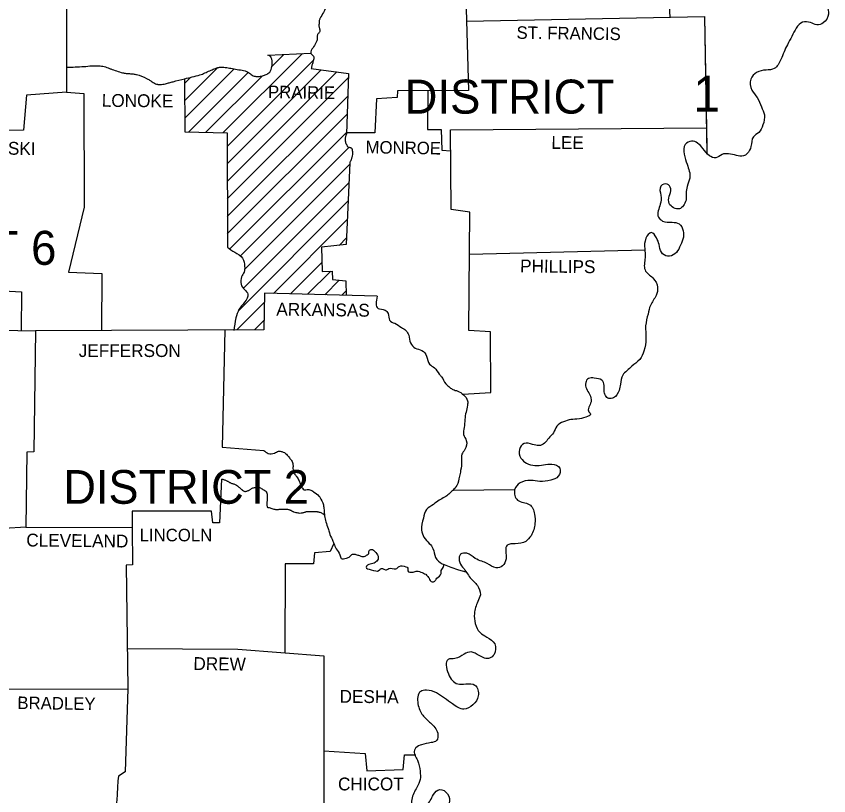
# Model space of a CAD drawing. Extents: x 982240 to 1103002, y 974866 to 1054902.
# Drawn here: x 1087558 to 1097361, y 1031353 to 1040761 of the extents above; entities that cross this region are included whole.
import ezdxf

# ---------------------------------------------------------------- set-up
doc = ezdxf.new("R2010")
doc.units = 0
for name, color, linetype in [('1', 7, 'Continuous'), ('Default', 7, 'Continuous'), ('R_Draft', 7, 'Continuous')]:
    doc.layers.add(name, color=color, linetype=linetype)

msp = doc.modelspace()

# ---------------------------------------------------------------- linework, layer by layer
at = {"layer": '1'}
for points in [[(1087926.5, 1048089), (1087933.9, 1047210.6), (1087872.7, 1047207), (1087883.5, 1046310.6), (1087631.5, 1046274.6), (1087653.1, 1046033.4), (1087739.5, 1045921.8), (1087732.3, 1045637.4), (1087242.7, 1045619.4), (1087224.7, 1045180.2), (1086778.3, 1045165.8), (1086756.7, 1044633), (1086781.9, 1044589.8), (1086792.7, 1043740.2), (1087563.1, 1043689.8), (1087552.3, 1041792.6), (1088164.3, 1041774.6), (1088164.3, 1039845), (1087681.9, 1039809), (1087645.9, 1039384.2), (1086835.9, 1039380.6)], [(1090594.2, 1040291.4), (1091112.1, 1040316.4)], [(1091116.2, 1040129.4), (1091566.2, 1040071.8), (1091541, 1039337.4)], [(1091580.6, 1038991.8), (1091537.4, 1038005.4), (1091242.2, 1037973), (1091249.4, 1037681.4), (1091368.2, 1037685), (1091371.8, 1037584.2), (1091533.8, 1037566.2), (1091539.1, 1037392.5)], [(1091911.8, 1037382.6), (1090551, 1037418.6), (1090543.8, 1036975.8), (1087789.9, 1036965)], [(1085716.3, 1036489.8), (1085917.9, 1036518.6), (1085932.3, 1036641), (1086051.1, 1036662.6), (1086058.3, 1036734.6), (1086897.1, 1036759.8), (1086929.5, 1036979.4), (1087789.9, 1036965)], [(1087674.7, 1034596.2), (1087148.3, 1034563.8)], [(1087674.7, 1034596.2), (1088957.3, 1034589)], [(1088957.3, 1034589), (1088959.9, 1034139), (1088884.3, 1034135.4), (1088905.9, 1032641.4)], [(1092721.8, 1034142.6), (1092802.4, 1034111), (1092894.8, 1034078.9), (1092982.6, 1034056.4)], [(1088905.9, 1032641.4), (1088869.9, 1031640.6), (1088790.7, 1031590.2)]]:
    msp.add_lwpolyline(points, dxfattribs=at)
for points in [[(1091573.4, 1042253.4), (1091571.2, 1042223.5), (1091568.5, 1042193.6), (1091563.7, 1042164), (1091560.1, 1042149.3), (1091557.9, 1042141.9), (1091555.4, 1042134.6), (1091543.7, 1042121.4), (1091525.3, 1042115.1), (1091504.8, 1042110.4), (1091495.2, 1042107.1), (1091487, 1042102.2), (1091444.9, 1042065.1), (1091407.8, 1042023), (1091401, 1042006), (1091399.3, 1041986.5), (1091397.4, 1041967.2), (1091389.8, 1041951), (1091383.2, 1041945.5), (1091375.5, 1041941.5), (1091357.9, 1041936.3), (1091340, 1041931.2), (1091325, 1041922.2), (1091308, 1041905), (1091291.9, 1041887), (1091277, 1041867.7), (1091263.8, 1041846.6), (1091239, 1041795.5), (1091224.2, 1041742.2), (1091221.3, 1041688.3), (1091224.2, 1041634.2), (1091226.7, 1041603.1), (1091231, 1041572.3), (1091238.1, 1041541.9), (1091243.2, 1041526.8), (1091249.4, 1041511.8), (1091266.2, 1041497.3), (1091291.2, 1041493.3), (1091317.8, 1041490.5), (1091339.4, 1041479.4), (1091346.6, 1041471.2), (1091353.2, 1041462.8), (1091365, 1041445.1), (1091382.6, 1041407.4), (1091383.5, 1041388.8), (1091378.2, 1041369.1), (1091373.3, 1041349.7), (1091375.4, 1041331.8), (1091392.2, 1041316), (1091417.1, 1041307.4), (1091442.8, 1041298.4), (1091461.8, 1041281.4), (1091468, 1041270.7), (1091473.6, 1041259.9), (1091476.9, 1041249.1), (1091476.2, 1041238.2), (1091461.8, 1041191.4), (1091422.2, 1041058.2), (1091419.4, 1041036.1), (1091421.2, 1041013.6), (1091424.4, 1040990.9), (1091425.8, 1040968.2), (1091424.3, 1040948.3), (1091422.1, 1040938.4), (1091418.6, 1040928.6), (1091399.7, 1040915.1), (1091371, 1040914.6), (1091341.8, 1040914.9), (1091321.4, 1040903.4), (1091263.8, 1040806.2), (1091224.2, 1040737.8), (1091219.3, 1040726.7), (1091211.9, 1040693), (1091210.6, 1040670.4), (1091209.8, 1040647.8), (1091211.5, 1040631.6), (1091216, 1040615.4), (1091220.2, 1040599.2), (1091220.6, 1040583), (1091215.6, 1040569.6), (1091207, 1040557.4), (1091198, 1040545.4), (1091191.8, 1040532.6), (1091189, 1040514), (1091188.4, 1040494.4), (1091186.8, 1040475), (1091181, 1040457), (1091145, 1040392.2), (1091112.6, 1040331), (1091113.9, 1040313.3), (1091127.9, 1040295.5), (1091143.3, 1040277.5), (1091148.6, 1040259), (1091143.6, 1040234.1), (1091137.8, 1040208.6), (1091132.2, 1040188.7), (1091125.9, 1040168.9), (1091116.2, 1040129.4)], [(1097203.6, 1042109.4), (1097218, 1042005), (1097156.9, 1041893.4), (1097135.3, 1041781.8), (1097146.1, 1041670.2), (1097030.9, 1041609), (1096930.1, 1041537), (1096987.7, 1041450.6), (1097095.7, 1041371.4), (1097203.6, 1041310.2), (1097272, 1041249), (1097290, 1041101.4), (1097308, 1041007.8), (1097344, 1040878.2), (1097358.4, 1040788.2), (1097293.6, 1040680.2), (1097218, 1040658.6), (1097138.9, 1040683.8), (1097045.3, 1040691), (1096969.7, 1040619), (1096915.7, 1040518.2), (1096861.7, 1040417.4), (1096822.1, 1040331), (1096782.5, 1040237.4), (1096703.3, 1040129.4), (1096606.1, 1040111.4), (1096490.9, 1040082.6), (1096422.5, 1040003.4), (1096433.3, 1039870.2), (1096498.1, 1039780.2), (1096548.5, 1039668.6), (1096584.5, 1039571.4), (1096566.5, 1039449), (1096516.1, 1039359), (1096451.3, 1039305), (1096422.5, 1039189.8), (1096375.7, 1039103.4), (1096332.5, 1039074.6), (1096246.1, 1039081.8), (1096152.5, 1039099.8), (1096073.3, 1039092.6), (1095997.7, 1039053), (1095922.1, 1039078.2), (1095842.9, 1039164.6), (1095778.1, 1039229.4), (1095706.1, 1039254.6), (1095630.5, 1039215), (1095616.1, 1039096.2), (1095652.1, 1038973.8), (1095684.5, 1038808.2), (1095652.1, 1038707.4), (1095641.3, 1038541.8)], [(1088164.3, 1040147), (1088373.1, 1040154.6), (1088571.1, 1040161.8), (1088634.8, 1040149.2), (1088665.9, 1040137.1), (1088681.4, 1040131.1), (1088697.1, 1040125.8), (1088841.1, 1040079), (1088861.7, 1040074.1), (1088882.8, 1040071.1), (1088925.6, 1040068.2), (1088968.4, 1040065.4), (1089010.3, 1040057.4), (1089129.1, 1040010.6), (1089146.8, 1040001.8), (1089164.2, 1039991.4), (1089198.4, 1039968.9), (1089250.9, 1039942.4), (1089260.1, 1039940.1), (1089269.4, 1039938.6), (1089291.5, 1039937.6), (1089359.2, 1039946.8), (1089404.6, 1039958.7), (1089449.4, 1039971), (1089589.8, 1040007), (1089773.4, 1040053.8), (1089803.9, 1040064), (1089833.3, 1040077.1), (1089862.5, 1040091.2), (1089892.2, 1040104.2), (1089909.1, 1040111.1), (1089959.8, 1040131.9), (1089994.1, 1040142.6), (1090011.5, 1040145.9), (1090029, 1040147.4), (1090097.3, 1040141.7), (1090165.8, 1040129.4), (1090243.5, 1040115.9), (1090320.6, 1040100.6), (1090346.7, 1040090.1), (1090370.6, 1040073.6), (1090393.9, 1040056.2), (1090417.8, 1040043), (1090460, 1040034.4), (1090506, 1040037), (1090552, 1040048.8), (1090573.8, 1040057.7), (1090594.2, 1040068.2), (1090615.9, 1040088.2), (1090632.1, 1040117.7), (1090646.3, 1040190.4), (1090634.5, 1040257.8), (1090618.1, 1040280.7), (1090594.2, 1040291.4)], [(1091541, 1039337.4), (1091536.9, 1039328.6), (1091533.5, 1039319.7), (1091528.9, 1039301.6), (1091526.7, 1039283.4), (1091526.4, 1039274.4), (1091526.6, 1039265.4), (1091529.4, 1039246), (1091535.6, 1039226.9), (1091544.5, 1039208.2), (1091549.7, 1039198.9), (1091555.4, 1039189.8), (1091560.4, 1039184.6), (1091566.8, 1039181.3), (1091581.8, 1039177.7), (1091596.2, 1039173.9), (1091601.9, 1039170.2), (1091604.1, 1039167.7), (1091605.8, 1039164.6), (1091607.5, 1039160.2), (1091609.1, 1039155.8), (1091614.6, 1039128.7), (1091615, 1039110.5), (1091614.3, 1039101.5), (1091613, 1039092.6), (1091606, 1039056.4), (1091601.2, 1039038.4), (1091598.3, 1039029.5), (1091595, 1039020.6), (1091588.4, 1039005.9), (1091580.6, 1038991.8)], [(1095641.3, 1038541.8), (1095558.5, 1038437.4), (1095436.1, 1038502.2), (1095436.1, 1038588.6), (1095454.1, 1038678.6), (1095410.9, 1038736.2), (1095335.3, 1038711), (1095335.3, 1038599.4), (1095328.1, 1038491.4), (1095306.5, 1038336.6), (1095356.9, 1038289.8), (1095472.1, 1038275.4), (1095554.9, 1038253.8), (1095605.3, 1038171), (1095601.7, 1038070.2), (1095562.1, 1037973), (1095504.5, 1037893.8), (1095414.5, 1037865), (1095342.5, 1037911.8), (1095313.7, 1038005.4), (1095281.3, 1038088.2), (1095220.1, 1038149.4), (1095155.3, 1038081), (1095140.9, 1037955), (1095144.5, 1037847), (1095144.5, 1037699.4), (1095238.1, 1037602.2), (1095295.7, 1037490.6), (1095277.7, 1037389.8), (1095209.3, 1037271), (1095180.5, 1037166.6), (1095151.7, 1037026.2), (1095155.3, 1036871.4), (1095130.1, 1036720.2), (1095079.7, 1036619.4), (1094986.1, 1036536.6), (1094924.9, 1036482.6), (1094874.5, 1036428.6), (1094849.3, 1036320.6), (1094831.3, 1036245), (1094762.9, 1036155), (1094708.9, 1036147.8), (1094665.7, 1036183.8), (1094651.3, 1036245), (1094651.3, 1036306.2), (1094622.5, 1036367.4), (1094532.5, 1036392.6), (1094460.5, 1036389), (1094428.1, 1036338.6), (1094474.9, 1036198.2), (1094492.9, 1036108.2), (1094467.7, 1035985.8), (1094482.1, 1035971.4), (1094352.5, 1035903), (1094248.1, 1035892.2), (1094161.7, 1035867), (1094078.9, 1035813), (1094039.3, 1035733.8), (1093981.7, 1035669), (1093931.3, 1035607.8), (1093862.9, 1035579), (1093787.3, 1035593.4), (1093686.5, 1035604.2), (1093628.9, 1035532.2), (1093646.9, 1035427.8), (1093715.3, 1035366.6), (1093816.1, 1035337.8), (1093920.5, 1035345), (1094021.3, 1035355.8), (1094114.9, 1035305.4), (1094096.9, 1035208.2), (1094006.9, 1035161.4), (1093873.7, 1035147), (1093765.7, 1035157.8), (1093636.1, 1035129), (1093571.3, 1035046.2), (1093607.3, 1034920.2), (1093747.7, 1034869.8), (1093812.5, 1034751), (1093816.1, 1034639.4), (1093769.3, 1034491.8), (1093704.5, 1034423.4), (1093578.5, 1034394.6), (1093481.3, 1034376.6), (1093466.9, 1034211), (1093423.7, 1034128.2), (1093348.1, 1034103), (1093240.1, 1034157), (1093175.3, 1034182.2), (1093096.2, 1034218.2), (1092995.4, 1034279.4), (1092919.8, 1034268.6), (1092941.4, 1034110.2), (1092948.6, 1034103), (1093035, 1033984.2), (1093121.4, 1033890.6), (1093161, 1033779)], [(1091911.8, 1037382.6), (1091922.6, 1037235), (1092009, 1037213.4), (1092045, 1037173.8), (1092063, 1037091), (1092124.2, 1037055), (1092207, 1037004.6), (1092257.4, 1036968.6), (1092293.4, 1036911), (1092315, 1036817.4), (1092372.6, 1036756.2), (1092451.8, 1036727.4), (1092509.4, 1036659), (1092545.4, 1036561.8), (1092603, 1036518.6), (1092660.6, 1036443), (1092689.4, 1036410.6), (1092739.8, 1036324.2), (1092790.2, 1036281), (1092826.2, 1036255.8), (1092883.8, 1036237.8), (1092955.8, 1036191), (1093002.6, 1036119), (1093002.6, 1036065), (1092984.6, 1035982.2), (1092970.2, 1035895.8), (1092963, 1035798.6), (1092955.8, 1035712.2), (1092988.2, 1035640.2), (1092970.2, 1035532.2), (1092934.2, 1035474.6), (1092930.6, 1035395.4), (1092919.8, 1035276.6), (1092905.4, 1035208.2), (1092873, 1035096.6), (1092826.2, 1035039)], [(1092826.2, 1035039), (1092725.4, 1034956.2), (1092660.6, 1034920.2), (1092592.2, 1034869.8), (1092509.4, 1034808.6), (1092469.8, 1034704.2), (1092448.2, 1034560.2), (1092477, 1034473.8), (1092541.8, 1034398.2), (1092585, 1034337), (1092617.4, 1034229), (1092696.6, 1034153.4), (1092721.8, 1034142.6)], [(1093161, 1033779), (1093125, 1033696.2), (1093085.4, 1033552.2), (1093096.2, 1033429.8), (1093150.2, 1033325.4), (1093236.5, 1033267.8), (1093330.1, 1033185), (1093322.9, 1033059), (1093268.9, 1033012.2), (1093143, 1033044.6), (1093045.8, 1033087.8), (1092963, 1033062.6), (1092851.4, 1033008.6), (1092768.6, 1032997.8), (1092772.2, 1032825), (1092883.8, 1032702.6), (1092981, 1032702.6), (1093092.6, 1032688.2), (1093132.2, 1032558.6), (1093067.4, 1032450.6), (1092959.4, 1032396.6), (1092822.6, 1032461.4), (1092725.4, 1032529.8), (1092628.2, 1032594.6), (1092505.8, 1032627), (1092437.4, 1032612.6), (1092405, 1032461.4), (1092462.6, 1032324.6), (1092556.2, 1032231), (1092642.6, 1032108.6), (1092628.2, 1032018.6), (1092563.4, 1031993.4), (1092448.2, 1031968.2), (1092379.8, 1031932.2), (1092361.8, 1031903.4), (1092397.8, 1031781), (1092430.2, 1031647.8), (1092430.2, 1031547), (1092390.6, 1031453.4), (1092329.4, 1031309.4), (1092336.6, 1031215.8), (1092379.8, 1031172.6), (1092433.8, 1031187), (1092505.8, 1031237.4), (1092552.6, 1031295), (1092592.2, 1031367), (1092667.8, 1031428.2), (1092761.4, 1031374.2), (1092783, 1031262.6), (1092729, 1031165.4), (1092653.4, 1031122.2), (1092559.8, 1031086.2), (1092491.4, 1031007), (1092509.4, 1030913.4), (1092563.4, 1030863), (1092696.6, 1030888.2), (1092786.6, 1030927.8), (1092837, 1030978.2), (1092898.2, 1031039.4), (1092930.6, 1031100.6), (1092977.4, 1031165.4), (1093060.2, 1031183.4), (1093099.8, 1031129.4), (1093085.4, 1031007), (1093035, 1030891.8), (1092966.6, 1030794.6), (1092891, 1030726.2), (1092797.4, 1030578.6), (1092815.4, 1030441.8), (1092851.4, 1030330.2), (1092901.8, 1030243.8), (1092988.2, 1030261.8), (1093085.4, 1030272.6), (1093143, 1030225.8), (1093135.8, 1030125), (1093063.8, 1030027.8), (1092995.4, 1029934.2), (1092959.4, 1029804.6), (1092973.8, 1029714.6), (1092973.8, 1029631.8), (1092945, 1029541.8), (1092894.6, 1029491.4), (1092761.4, 1029495), (1092621, 1029509.4), (1092545.4, 1029466.2), (1092559.8, 1029343.8), (1092642.6, 1029253.8), (1092700.2, 1029207), (1092783, 1029106.2), (1092819, 1029023.4), (1092808.2, 1028951.4), (1092757.8, 1028890.2), (1092610.2, 1028818.2)], [(1088790.7, 1031590.2), (1088779.9, 1031478.6), (1088776.3, 1031374.2), (1088769.1, 1031273.4), (1088767.1, 1031235.6), (1088767.3, 1031216.7), (1088769.1, 1031197.8), (1088776.3, 1031175.9), (1088788.6, 1031155.8), (1088802, 1031136), (1088812.3, 1031115), (1088837.5, 1031035.8), (1088862.7, 1030967.4), (1088913.1, 1030877.4), (1088924.3, 1030860.1), (1088936.3, 1030843.3), (1088948.5, 1030826.5), (1088959.9, 1030809), (1088978.2, 1030760.7), (1088979.8, 1030735.4), (1088974.3, 1030711.8), (1088945.5, 1030661.4), (1088932.2, 1030642.2), (1088918.3, 1030623.5), (1088904.4, 1030604.8), (1088891.5, 1030585.8), (1088885.4, 1030553), (1088893.2, 1030515.3), (1088899.1, 1030478.7), (1088887.9, 1030449), (1088880.4, 1030442.5), (1088872.5, 1030436.8), (1088855.7, 1030426.7), (1088838.8, 1030417), (1088823.1, 1030405.8), (1088782.3, 1030369.1), (1088761.8, 1030350.9), (1088740.3, 1030333.8), (1088693.5, 1030301.4), (1088643.1, 1030269), (1088628.2, 1030256.2), (1088615.2, 1030241.1), (1088602.6, 1030225.7), (1088589.1, 1030211.4), (1088569.9, 1030197.3), (1088548.9, 1030185.2), (1088528.2, 1030172.7), (1088509.9, 1030157.4), (1088493.8, 1030136.3), (1088480.4, 1030113), (1088467.4, 1030089.4), (1088452.3, 1030067.4), (1088437.3, 1030049.1), (1088422, 1030031.1), (1088387.5, 1029999), (1088333.5, 1029963), (1088314.6, 1029951.5), (1088295.5, 1029940.6), (1088267.1, 1029923), (1088257.9, 1029916.2), (1088244.8, 1029901.5), (1088236.3, 1029883.6), (1088225.5, 1029844.2), (1088215.9, 1029811), (1088207.3, 1029777.8), (1088201.4, 1029744.5), (1088200.3, 1029711), (1088204.7, 1029662.3), (1088211.1, 1029613.8), (1088225.5, 1029527.4), (1088223.9, 1029500.4), (1088216.5, 1029473.4), (1088209.1, 1029446.4), (1088207.5, 1029419.4), (1088225.5, 1029300.6), (1088243.5, 1029207), (1088272.3, 1029124.2), (1088311.9, 1029030.6), (1088335.4, 1028986.5), (1088362.3, 1028944.2), (1088407.4, 1028882.8), (1088457.1, 1028825)]]:
    msp.add_spline(points, degree=3, dxfattribs=at)
at = {"layer": 'Default'}
msp.add_line((1092826.2, 1035039.3), (1093572.9, 1035050.5), dxfattribs=at)
for points in [[(1095381.9, 1042371.7), (1095400.1, 1040971.8), (1095432.5, 1040950.2), (1095444, 1040751)], [(1092959.4, 1041835.8), (1093013.4, 1039863), (1092156.6, 1039859.4), (1092153, 1039780.2), (1091904.6, 1039765.8), (1091883, 1039355.4), (1091541.6, 1039355.4)], [(1092990.4, 1040701.6), (1095860.9, 1040759.4)], [(1095860.9, 1040759.4), (1095889.7, 1039182.6)], [(1095860.9, 1040759.4), (1095889.7, 1039182.6)], [(1095860.9, 1040759.4), (1095889.7, 1039182.6)], [(1095860.9, 1040759.4), (1095889.7, 1039182.6)], [(1095860.9, 1040759.4), (1095889.7, 1039182.6)], [(1095860.9, 1040759.4), (1095889.7, 1039182.6)], [(1095860.9, 1040759.4), (1095889.7, 1039182.6)], [(1095860.9, 1040759.4), (1095891, 1039110.4)], [(1089586.2, 1040010.6), (1089593.4, 1039366.2), (1090101, 1039355.4), (1090104.6, 1037973)], [(1088164.3, 1039845), (1088373.1, 1039830.6), (1088376.7, 1038455.4), (1088189.5, 1037674.2), (1088589.1, 1037656.2), (1088585.3, 1036968.1)], [(1092523.9, 1039861), (1092520.2, 1039395), (1092685.8, 1039395), (1092693, 1039146.6), (1092799.3, 1039135.6)], [(1092947.5, 1036198.3), (1093283.3, 1036219.8), (1093279.7, 1036950.6), (1093017, 1036968.6), (1093031.4, 1038397.8), (1092804.6, 1038430.2), (1092797.4, 1039391.4), (1095885.5, 1039413.1)], [(1085359.9, 1038946.6), (1085788.3, 1038919.8), (1085773.9, 1038469.8), (1086245.5, 1038451.8), (1086252.7, 1038059.4), (1086475.9, 1038041.4), (1086475.9, 1037973), (1086684.7, 1037958.6), (1086691.9, 1037706.6), (1087167.1, 1037706.6), (1087181.5, 1037458.2), (1087620.7, 1037436.6), (1087617.1, 1036967.9)], [(1093026.2, 1037889.9), (1095141.4, 1037942.4)], [(1087789.9, 1036965), (1087768.3, 1035503.4), (1087685.5, 1035499.8), (1087674.7, 1034596.2)], [(1090073.4, 1036974), (1090043.4, 1035561), (1090543.8, 1035521.4)], [(1090032.6, 1035175.8), (1090011, 1034646.6), (1089928.2, 1034646.6), (1089913.8, 1034787), (1088956.3, 1034787), (1088957.3, 1034589)], [(1091389.8, 1034398.2), (1091346.6, 1034301), (1091155.8, 1034283), (1091145, 1034153.4), (1090803, 1034153.4), (1090799.4, 1033077)], [(1088895.1, 1033131), (1090230.6, 1033120.2), (1091267.4, 1033041)], [(1091267.4, 1033041), (1091267.4, 1030888.2), (1091296.2, 1028820.4)], [(1087278.7, 1032637.8), (1088905.9, 1032641.4)], [(1091267.4, 1031893.7), (1091767.8, 1031863.8), (1091789.4, 1031655), (1092225, 1031669.4), (1092243, 1031845.8), (1092377.6, 1031845.8)]]:
    msp.add_lwpolyline(points, dxfattribs=at)
for points in [[(1090104.6, 1037973), (1090194.6, 1037911.8), (1090288.2, 1037839.8), (1090313.4, 1037742.6), (1090306.2, 1037674.2), (1090277.4, 1037616.6), (1090270.2, 1037526.6), (1090313.4, 1037461.8), (1090353, 1037407.8), (1090313.4, 1037310.6), (1090245, 1037220.6), (1090209, 1037119.8), (1090183.8, 1036968.6)], [(1090543.8, 1035521.4), (1090597.8, 1035485.4), (1090673.4, 1035489), (1090723.8, 1035510.6), (1090763.4, 1035507), (1090817.4, 1035474.6), (1090853.4, 1035431.4), (1090878.6, 1035399), (1090896.6, 1035348.6), (1090896.6, 1035301.8), (1090914.6, 1035237), (1090936.2, 1035211.8), (1090965, 1035165), (1090983, 1035121.8), (1090993.8, 1035093), (1091033.4, 1035046.2), (1091069.4, 1035049.8), (1091101.8, 1035046.2), (1091145, 1035021), (1091209.8, 1034970.6), (1091220.6, 1034956.2), (1091263.8, 1034862.6), (1091271, 1034805), (1091278.2, 1034729.4), (1091292.6, 1034657.4), (1091321.4, 1034578.2), (1091335.8, 1034524.2), (1091368.2, 1034448.6), (1091389.8, 1034398.2), (1091418.6, 1034333.4), (1091461.8, 1034261.4), (1091479.8, 1034218.2), (1091541, 1034221.8), (1091584.2, 1034239.8), (1091616.6, 1034268.6), (1091656.2, 1034265), (1091699.4, 1034250.6), (1091757, 1034239.8), (1091793, 1034261.4), (1091811, 1034275.8), (1091814.6, 1034308.2), (1091847, 1034326.2), (1091883, 1034301), (1091922.6, 1034243.4), (1091922.6, 1034207.4), (1091908.2, 1034185.8), (1091861.4, 1034157), (1091796.6, 1034135.4), (1091778.6, 1034110.2), (1091839.8, 1034081.4), (1091937, 1034074.2), (1091962.2, 1034095.8), (1092027, 1034077.8), (1092052.2, 1034095.8), (1092138.6, 1034092.2), (1092178.2, 1034121), (1092257.4, 1034117.4), (1092282.6, 1034099.4), (1092282.6, 1034067), (1092347.4, 1034052.6), (1092394.2, 1034063.4), (1092455.4, 1034045.4), (1092509.4, 1034016.6), (1092538.2, 1033977), (1092574.2, 1033933.8), (1092606.6, 1033944.6), (1092631.8, 1033977), (1092685.8, 1034034.6), (1092685.8, 1034070.6), (1092700.2, 1034095.8), (1092721.8, 1034142.6)], [(1090032.6, 1035175.8), (1090049.3, 1035172.3), (1090065.7, 1035167.3), (1090097.4, 1035154.2), (1090109.4, 1035148.1), (1090120.9, 1035141.6), (1090132.5, 1035135), (1090144.2, 1035129), (1090159.4, 1035123.3), (1090175.1, 1035118.9), (1090190.7, 1035114.1), (1090205.4, 1035107.4), (1090225.7, 1035093.6), (1090245, 1035078.6), (1090258.6, 1035067.1), (1090271.7, 1035054.7), (1090285, 1035042.6), (1090291.9, 1035037), (1090299, 1035031.8), (1090313.9, 1035026.7), (1090330.7, 1035027.8), (1090347.9, 1035032.6), (1090363.8, 1035039), (1090375.6, 1035045.8), (1090386.7, 1035054.1), (1090398, 1035062.1), (1090410.6, 1035067.8), (1090457.4, 1035075), (1090493.4, 1035071.4), (1090533, 1035049.8), (1090556.5, 1035036.4), (1090567.2, 1035028.4), (1090572, 1035023.3), (1090574.2, 1035020.5), (1090576.2, 1035017.4), (1090583.3, 1034994.3), (1090583.6, 1034982.5), (1090583.4, 1034970.6), (1090583.4, 1034916.6), (1090583.4, 1034841), (1090586.1, 1034835.8), (1090592.7, 1034833.2), (1090608.6, 1034830.2), (1090653.3, 1034816.3), (1090698.6, 1034808.6), (1090713.9, 1034808.9), (1090729.2, 1034810.1), (1090744.5, 1034811.4), (1090759.8, 1034812.2), (1090788.6, 1034812.7), (1090817.4, 1034812.2), (1090841.1, 1034808.7), (1090852.7, 1034805.4), (1090864.2, 1034801.4), (1090874.4, 1034796.5), (1090884, 1034790.3), (1090893.6, 1034784.3), (1090903.8, 1034779.8), (1090932.6, 1034772.6), (1090975.8, 1034765.4), (1091011.8, 1034769), (1091027.2, 1034772.8), (1091042.3, 1034777.5), (1091057.5, 1034781.7), (1091073, 1034783.4), (1091109, 1034783.4), (1091166.6, 1034783.4), (1091184.6, 1034782.3), (1091193.6, 1034781.2), (1091202.6, 1034779.8), (1091241.1, 1034765.5), (1091259.3, 1034754.4), (1091276.8, 1034742.5)]]:
    msp.add_spline(points, degree=3, dxfattribs=at)
at = {"layer": 'R_Draft'}
for p, q in [((1090054.8, 1039356.4), (1091009.8, 1040311.5)), ((1090101.5, 1039191), (1091143.3, 1040232.8)), ((1090642.6, 1040156.4), (1090786.9, 1040300.7)), ((1089589.3, 1039739.4), (1089991.8, 1040142)), ((1089591.6, 1039529.7), (1090187.6, 1040125.6)), ((1089639.3, 1039365.2), (1090357.2, 1040083.1)), ((1089847, 1039360.8), (1090527.9, 1040041.6)), ((1090102, 1038979.4), (1091236.6, 1040114)), ((1090102.6, 1038767.8), (1091424.7, 1040089.9)), ((1089586.9, 1039949.2), (1089663.5, 1040025.8)), ((1090103.1, 1038556.2), (1091564.3, 1040017.4)), ((1090103.7, 1038344.6), (1091556.8, 1039797.8)), ((1090104.2, 1038133.1), (1091549.3, 1039578.1)), ((1090135.4, 1037952.1), (1091541.7, 1039358.4)), ((1090261.2, 1037865.8), (1091574.8, 1039179.4)), ((1090312.1, 1037704.5), (1091579.7, 1038972.2)), ((1090300.2, 1037480.5), (1091570, 1038750.3)), ((1090238.1, 1037206.3), (1091560.3, 1038528.5)), ((1090659.7, 1037415.7), (1091550.6, 1038306.6)), ((1091452.1, 1037996.1), (1091540.9, 1038084.8)), ((1090866.3, 1037410.3), (1091246.7, 1037790.6)), ((1091073, 1037404.8), (1091352.8, 1037684.5)), ((1091279.7, 1037399.3), (1091455.3, 1037574.9)), ((1091486.3, 1037393.9), (1091537.5, 1037445)), ((1090218.5, 1036974.5), (1090549.2, 1037305.2)), ((1090431.4, 1036975.4), (1090545.7, 1037089.6))]:
    msp.add_line(p, q, dxfattribs=at)

# ---------------------------------------------------------------- texts
at = {"layer": 'Default'}
for s, height, rotation, p in [('ST. FRANCIS', 151.176, 359.22155, (1093592.9, 1040489.4)), ('PRAIRIE', 151.22, 359.21156, (1090594.2, 1039773)), ('LONOKE', 154.82, 359.49741, (1088589.1, 1039668.6)), ('PULASKI', 154.83, 359.05303, (1086915.1, 1039099.8)), ('MONROE', 151.18, 359.03305, (1091771.4, 1039107)), ('LEE', 154.82, 359.43272, (1094014.1, 1039161)), ('PHILLIPS', 154.78, 359.31792, (1093636.1, 1037670.6)), ('ARKANSAS', 154.78, 359.26781, (1090695, 1037148.6)), ('CLEVELAND', 154.82, 359.33764, (1087678.3, 1034362.2)), ('DREW', 154.78, 359.22576, (1089694.2, 1032871.8)), ('DESHA', 154.78, 359.37039, (1091458.2, 1032475.8)), ('BRADLEY', 151.18, 359.14488, (1087570.3, 1032400.2))]:
    msp.add_text(s, height=height, rotation=rotation, dxfattribs=at).set_placement(p)
for s, height, p in [('1', 432, (1095727.7, 1039611)), ('DISTRICT', 410.4, (1092243, 1039585.8)), ('DISTRICT 6', 410.4, (1085054, 1037760.6)), ('JEFFERSON', 154.8, (1088311.9, 1036648.2)), ('DISTRICT 2', 406.79, (1088126.2, 1034876.7)), ('LINCOLN', 151.2, (1089046.3, 1034423.4)), ('CHICOT', 154.8, (1091440.2, 1031417.4))]:
    msp.add_text(s, height=height, dxfattribs=at).set_placement(p)

doc.saveas('drawing.dxf')
